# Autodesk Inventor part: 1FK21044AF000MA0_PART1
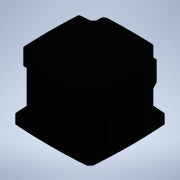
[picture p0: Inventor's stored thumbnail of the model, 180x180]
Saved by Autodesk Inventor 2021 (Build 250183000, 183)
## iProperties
Created: 2025-04
Part Number: 1FK21044AF000MA0_PART1
Material: Generic
Catalog Web Link: www.3dfindit.com
Description: -Servo synchronous motor
Document SubType Name: Modeling
Designer: psAdmin
Mass: 314.393 g
Surface Area: 353.669 cm^2
Volume: 314.393 cm^3
Density: 1 g/cm^3
Appearance: PSOLRGB-176-176-176
Category: PARTsolutions
Title: 1FK21044AF000MA0_PART1
Author: Cadenas PARTsolutions
Comments: Servo synchronous motor
Sending System: PARTsolutions
Preprocessor: ST-DEVELOPER v19.3
PSOL_IDENT_0: {$CADENAS_DATA/23d-libs/siemens_ag/_cat_/39/c4/1fk21044af000ma0.prj},213 {VTYP=3D},{NB=1FK21044AF000
PSOL_IDENT_1: MA0_PART1},{LINA=1FK21044AF000MA0_PART1},{NN=1FK21044AF000MA0_PART1},{NOPRJ=TRUE},{DATE=19.08.2025 1
PSOL_IDENT_2: 4:00:33},{GEOMDATE=30.07.2025 02:02:22},{VERSION=},{LINEID=10},{WBVAR=},{WBNUMERIC=}  {NB=1FK21044AF
PSOL_IDENT_3: 000MA0_PART1},{LINA=1FK21044AF000MA0_PART1},{KT=DUMMY},{PREVIEW=../../../_pool_/cb/72/p_d211_xx_0043
PSOL_IDENT_4: 4j.png},{DESCSHORT=SIMOTICS S-1FK2 HD, SINAMICS S210 3AC 400V-480V, 1.27 Nm, 3000 rpm},{DESCLONG=SIM
PSOL_IDENT_5: OTICS S-1FK2 HD servo motor M0=1.27 Nm; PN = 0.4 kW at nN=3000 rpm (380-480 V); PN = 0.2 kW at nN=15
PSOL_IDENT_6: 00 rpm (200-240 V); degree of protection IP64; cylindrical shaft D19x40mm; absolute encoder 22-bit +
PSOL_IDENT_7: 12-bit multiturn (encoder AM22DQC); with OCC interface; plug size M17, rotatable; SIMOTICS S-1FK2 s
PSOL_IDENT_8: ervomotorfor a wide range of uses in industrial environments. SIMOTICS S‑1FK2 servomotors are compac
PSOL_IDENT_9: t synchronous motors with a high dynamic performance that set themselves apart as a result of their
PSOL_IDENT_10: high power density, degree of protection and overload capability. The motors are available in two va
PSOL_IDENT_11: riants: as High Dynamic variant (highest dynamic performance as a result of the low intrinsic moment
PSOL_IDENT_12: of inertia for applications demanding a high dynamic performance with low moved masses) - and as Co
PSOL_IDENT_13: mpact variant (precise and stable closed-loop control for medium up to large moved masses as a resul
PSOL_IDENT_14: t of a medium intrinsic moment of inertia). SIMOTICSS‑1FK2 servomotors fully exploit their strengths
PSOL_IDENT_15: in a system with the SINAMICSS210 frequency converter and simple connection using the one cable con
PSOL_IDENT_16: nection (OCC). Advantages include the short control and positioning times, fast and precise correcti
PSOL_IDENT_17: on of disturbing quantities as well as stable control with a high dynamic performance. The servo mot
PSOL_IDENT_18: ors can be configured to address a wide range of requirements. For example with and without holding
PSOL_IDENT_19: brake, IP64 or IP65 degree of protection, singleturn or multiturn absolute encoders - to name just a
PSOL_IDENT_20: few. Further, the servomotors are available in different shaft heights extending from 20 to 100. A
PSOL_IDENT_21: shaft sealing ring is available to achieve an IP65 degree of protection and for subsequent mounting
PSOL_IDENT_22: at the motor or as spare part. SIMOTICS - the optimum motor for each and every motion control applic
PSOL_IDENT_23: ation.},{INTNO=804766906428},{SUPPLIERALTNO=1FK2104-4AF00-0MA0},{MANUID=1FK21044AF000MA0},{MANUNAME=
PSOL_IDENT_24: Siemens},{MANUTYPEDESC=Synchronous motor 1FK2-HD 1.27 NM},{AAU732=SIMOTICS},{AAO057=S-1FK2},{AAU734=
PSOL_IDENT_25: SIMOTICS S-1FK2 HD servo motor M0=1.27 Nm; PN = 0.4 kW at nN=3000 rpm (380-480 V); PN = 0.2 kW at nN=
PSOL_IDENT_26: 1500 rpm (200-240 V); degree of protection IP64; cylindrical shaft D19x40mm; absolute encoder 22-bit
PSOL_IDENT_27: + 12-bit multiturn (encoder AM22DQC); with OCC interface; plug size M17, rotatable;},{AAW338=Synchr
PSOL_IDENT_28: onous motor 1FK2-HD 1.27 NM},{AAO742=SIMOTICS},{AAO663=4042948693322},{NOCUPEROU=1},{PRICEQUANTITY=1
PSOL_IDENT_29: },{QUANTITYMIN=1},{QUANTITYINT=1},{CTN=85015100},{COO=DE},{AAO676=1FK2104-4AF00-0MA0},{AAO677=Siemen
PSOL_IDENT_30: s AG},{ORDERUNIT=C62},{CONTENTUNIT=C62}
NB: 1FK21044AF000MA0_PART1
NT: Servo synchronous motor
NBSYN: $MANUID._PART1
LINA: 1FK21044AF000MA0_PART1
CATALOG: SIEMENS
PREVIEW: ../../../_pool_/cb/72/p_d211_xx_00434j.png
DESCSHORT: SIMOTICS S-1FK2 HD, SINAMICS S210 3AC 400V-480V, 1.27 Nm, 3000 rpm
DESCLONG: SIMOTICS S-1FK2 HD servo motor M0=1.27 Nm; PN = 0.4 kW at nN=3000 rpm (380-480 V); PN = 0.2 kW at nN=1500 rpm (200-240 V); degree of protection IP64; cylindrica
INTNO: 804766906428
SUPPLIERALTNO: 1FK2104-4AF00-0MA0
MANUID: 1FK21044AF000MA0
MANUNAME: Siemens
MANUTYPEDESC: Synchronous motor 1FK2-HD 1.27 NM
AAU732: SIMOTICS
AAO057: S-1FK2
AAU734: SIMOTICS S-1FK2 HD servo motor M0=1.27 Nm; PN = 0.4 kW at nN=3000 rpm (380-480 V); PN = 0.2 kW at nN=1500 rpm (200-240 V); degree of protection IP64; cylindrica
AAW338: Synchronous motor 1FK2-HD 1.27 NM
AAO742: SIMOTICS
AAO663: 4042948693322.0
NOCUPEROU: 1
PRICEQUANTITY: 1
QUANTITYMIN: 1
QUANTITYINT: 1
CTN: 85015100
COO: DE
ARTICLENO: 1FK21044AF000MA0_PART1
BOMINFO: 1FK21044AF000MA0_PART1
CREATOR: CADENAS GmbH
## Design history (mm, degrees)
feature "2025_04_17_15_01_27_0882"
node "ECLASS_CAX_IMPORTER_001_CP_0_XY"
node "ECLASS_CAX_IMPORTER_001_CP_0_YZ"
node "ECLASS_CAX_IMPORTER_001_CP_0_ZX"
node "ECLASS_CAX_IMPORTER_001_CP_0_X"
node "ECLASS_CAX_IMPORTER_001_CP_0_Y"
node "ECLASS_CAX_IMPORTER_001_CP_0_Z"
node "ECLASS_CAX_IMPORTER_001_CP_0_Center"
node "ECLASS_CAX_IMPORTER_001_CP_1_XY"
node "ECLASS_CAX_IMPORTER_001_CP_1_YZ"
node "ECLASS_CAX_IMPORTER_001_CP_1_ZX"
node "ECLASS_CAX_IMPORTER_001_CP_1_X"
node "ECLASS_CAX_IMPORTER_001_CP_1_Y"
node "ECLASS_CAX_IMPORTER_001_CP_1_Z"
node "ECLASS_CAX_IMPORTER_001_CP_1_Center"
body "Solid1"
